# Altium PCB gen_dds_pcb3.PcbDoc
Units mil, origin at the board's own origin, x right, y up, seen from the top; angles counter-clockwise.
Board outline 6000 x 4000 mil, 2 copper layers (Top Layer, Bottom Layer); 13 components, 10 nets, 45 pads, 6 vias.
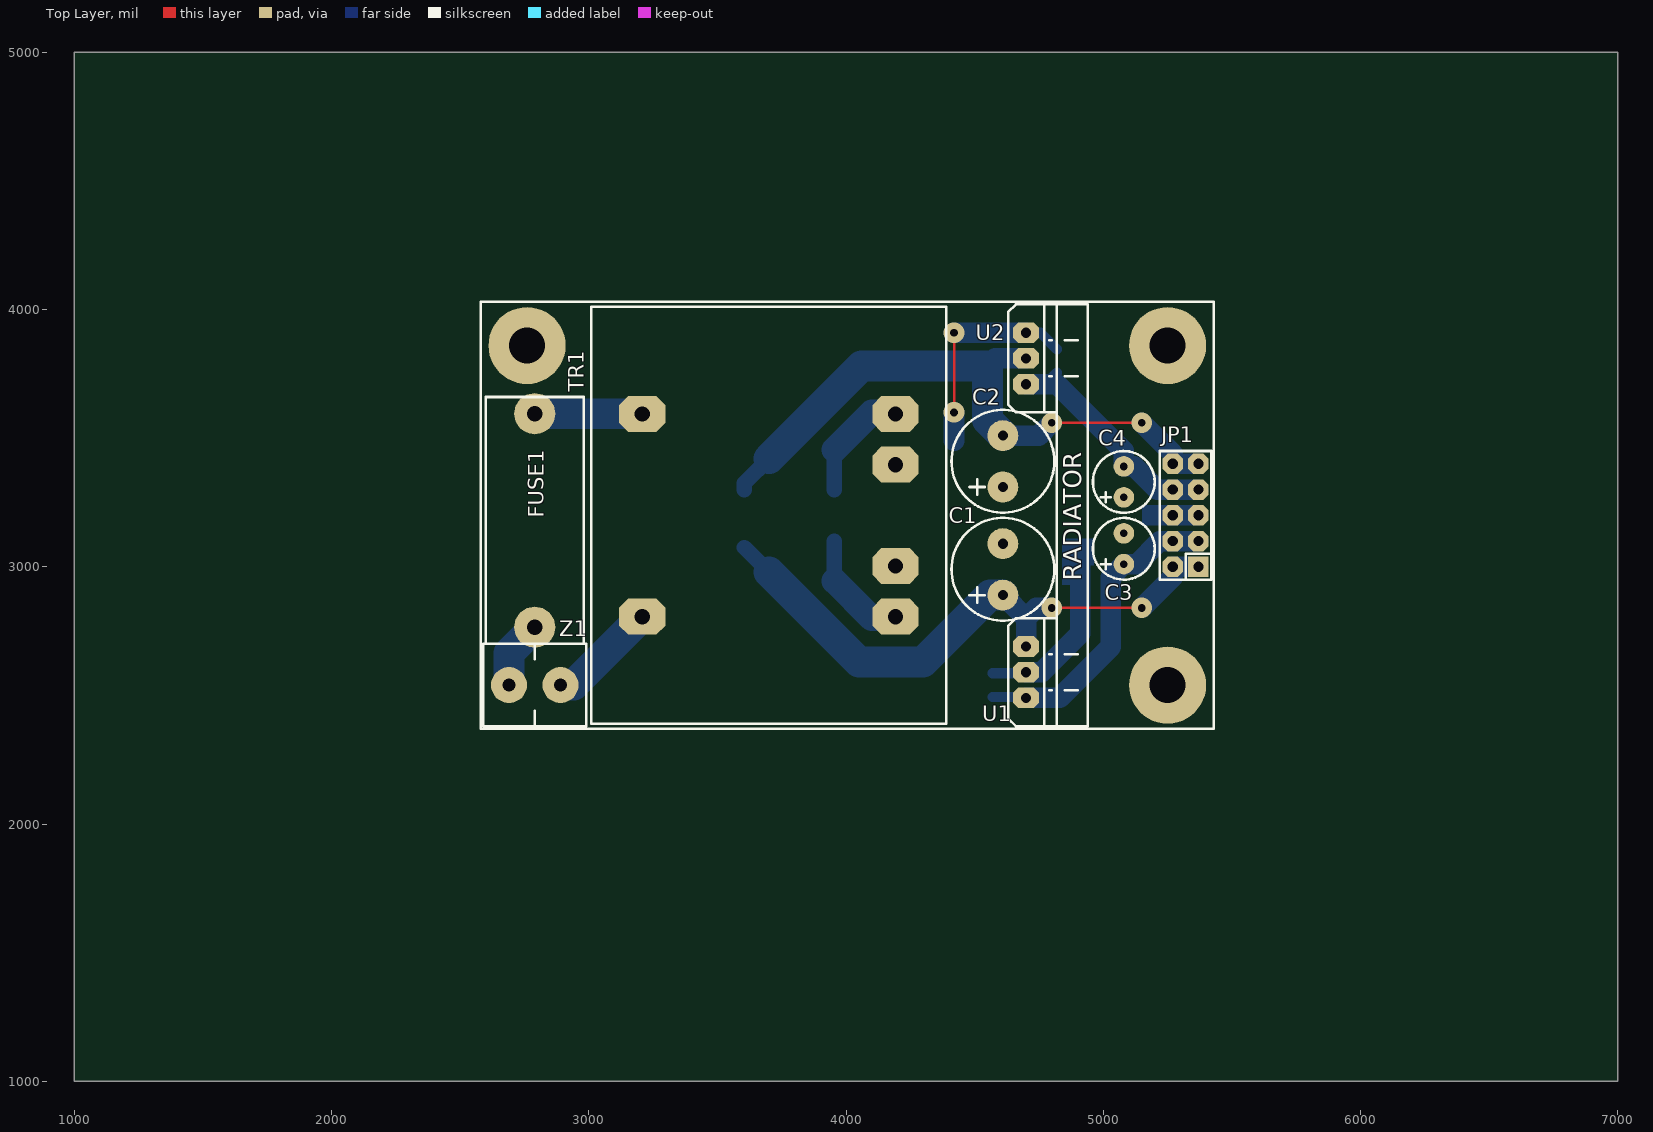
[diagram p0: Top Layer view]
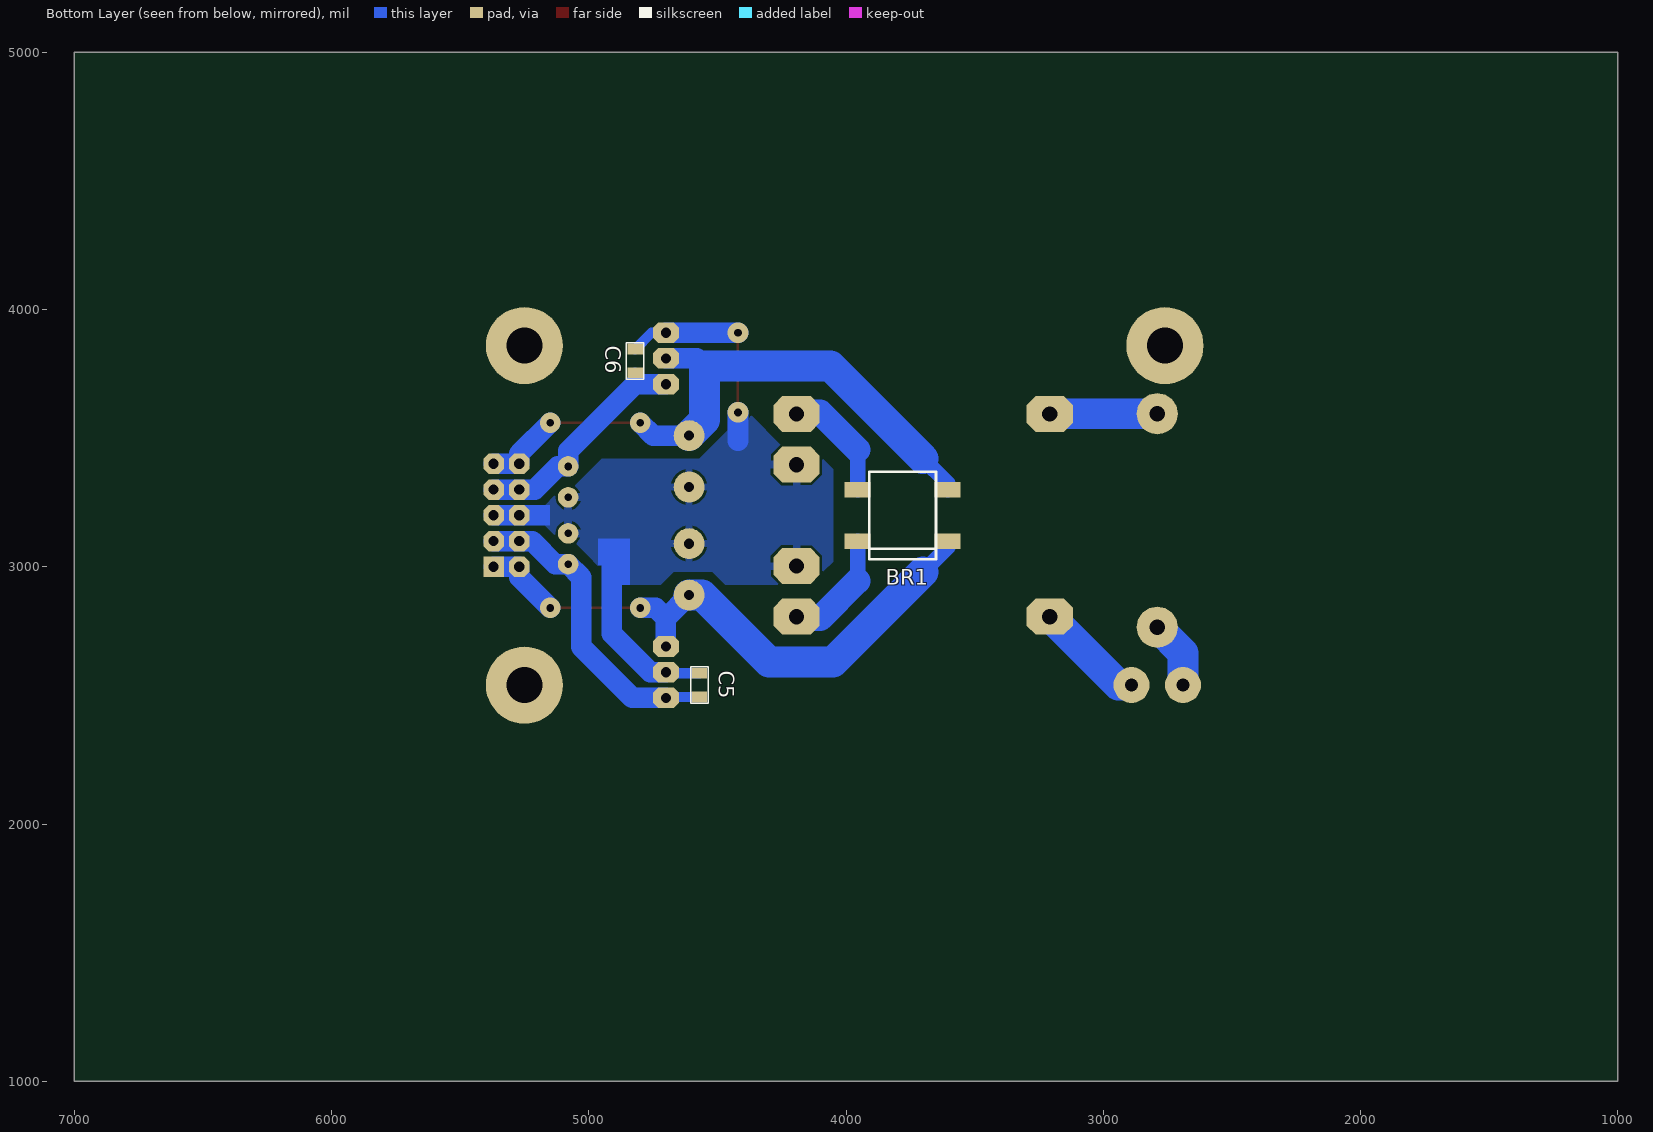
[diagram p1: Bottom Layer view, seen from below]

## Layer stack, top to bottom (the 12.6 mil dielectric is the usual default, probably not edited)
Top Layer: signal copper 1.4
Dielectric: dielectric 12.6, FR-4, Dk 4.8
Bottom Layer: signal copper 1.4

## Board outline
1000,1000 7000,1000 7000,5000 1000,5000

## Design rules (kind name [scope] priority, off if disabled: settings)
Clearance [All] p1: gap=10
PlaneConnect [All] p1: planeconnectstyle=Relief reliefexpansion=20 reliefentries=4 reliefconductorwidth=30 reliefairgap=10
PolygonConnect [All] p1: connectstyle=Relief reliefconductorwidth=30 reliefentries=4 polygonreliefangle="90 Angle"
RoutingVias [All] p1: holewidth=28 width=50 viastyle="Through Hole" minholewidth=28 minwidth=50 maxholewidth=28 maxwidth=50
SilkscreenOverComponentPads [All] p1: minsilkscreentomaskgap=10
SolderMaskExpansion [All] p1: expansion=4
Width [All] p1: maxlimit=200 minlimit=10 preferedwidth=40 toplayer_maxwidth=10 toplayer_prefwidth=10 bottomlayer_minwidth=20 minimp=50.000000 maximp=50.000000 favimp=50.000000
26 further rules are at their usual default settings.

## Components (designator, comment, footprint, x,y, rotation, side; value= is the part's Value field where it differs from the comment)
BR1 "SDB106" SDB1 3780,3200 r0 bottom
C1 "1500u" CE10 4610,2990 r90 top
C2 "1500u" CE10 4610,3410 r90 top
C3 "100u" CE6 5080,3070 r90 top
C4 "100u" CE6 5080,3330 r90 top
C5 "100n" 0805 4570,2540 r90 bottom
C6 "100n" 0805 4820,3800 r270 bottom
FUSE1 "250mA" FUSE 2790,3180 r90 top
JP1 "G2*5" G2*5 5370,3000 r180 top
TR1 "V38AJ-14D06P7" V38AJ-14D06P7 3700,3200 r0 top
U1 "7805" TO220V 4700,2590 r270 top
U2 "7905" TO220V 4700,3810 r270 top
Z1 "ARK2" ARK2 2690,2540 r0 top

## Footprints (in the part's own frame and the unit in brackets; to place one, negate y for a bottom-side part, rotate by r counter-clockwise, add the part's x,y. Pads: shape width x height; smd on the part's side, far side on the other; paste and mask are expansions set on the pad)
0805 [mil]
  rect 42x60 smd: 1(-46,0) 2(46,0)
  silkscreen extent -71,-34 71,34
ARK2 [mil]
  round 140 hole 50: 1(0,0) 2(200,0)
  silkscreen extent -100,-160 300,160
CE6 [mil] "6mm, raster 3mm, pad 2mm"
  round 80 hole 30: 1(-60,0) 2(60,0)
  silkscreen extent -120,-120 120,120
CE10 [mil] "10mm, raster 5mm, pad 3mm"
  round 120 hole 40: 1(-100,0) 2(100,0)
  silkscreen extent -200,-200 200,200
FUSE [mil]
  round 160 hole 60: 1(-415,0) 2(415,0)
  silkscreen extent -480,-190 480,190
G2*5 [mil]
  rect 80x80 hole 40: 1(0,0)
  oct 80x80 hole 40: 2(100,0) 3(0,-100) 4(100,-100) 5(0,-200) 6(100,-200) 7(0,-300) 8(100,-300) 9(0,-400) 10(100,-400)
  silkscreen extent -50,-450 150,50
SDB1 [mil]
  rect 100x60 smd: 1(175,-100) 2(175,100) 3(-175,100) 4(-175,-100)
  silkscreen extent -130,-170 130,170
TO220V [mil]
  oct 80x100 hole 40: 1(-100,0) 2(0,0) 3(100,0)
  silkscreen extent -210,-70 210,120
V38AJ-14D06P7 [mil]
  oct 180x140 hole 60 unplated: 1(-492.5,394) 2(-492.5,-394) 3(492.5,394) 4(492.5,197) 5(492.5,-197) 6(492.5,-394)
  silkscreen extent -690,-810 690,810

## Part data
BR1: library part "MOSTEK GRETZA"
C1 C2 C3 C4: library part CE
C5 C6: library part C
FUSE1: library part FUSE
TR1: library part TRANSFORMATOR2

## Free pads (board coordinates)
  round 300 hole 140: 0(2760,3860) 1(5250,3860) 2(5250,2540)

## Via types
v1: diameter 80, hole 30, Top Layer to Bottom Layer, 6 vias

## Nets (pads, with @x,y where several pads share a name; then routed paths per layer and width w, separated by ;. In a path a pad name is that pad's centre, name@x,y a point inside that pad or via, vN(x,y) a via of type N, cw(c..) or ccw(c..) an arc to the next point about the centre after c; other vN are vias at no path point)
+5V: C3.1 C5.1 JP1.3 JP1.4 U1.3 | length 1206.8
  Bottom Layer w40: C5.1 U1.3@4696,2494
  Bottom Layer w80: U1.3 4830,2490 5030,2690 5030,2960 C3.1 5130,3010 5220,3100 JP1.4 JP1.3
+ZAS: BR1.3 C1.1 JP1.1 JP1.2 U1.1 | length 2310.6
  Top Layer w10: v1(4800,2840) v1(5150,2840)
  Bottom Layer w60: BR1.3@3605,3075 3700,2980
  Bottom Layer w80: C1.1 4700,2800 ; U1.1 4700,2800 ; v1(4800,2840) 4740,2840 4700,2800 ; v1(5150,2840) 5270,2960 JP1.2 JP1.1
  Bottom Layer w120: 3700,2980 4050,2630 4300,2630 4560,2890 C1.1
-5V: C4.2 C6.2 JP1.7 JP1.8 U2.3 | length 937.2
  Bottom Layer w40: 4776,3710 C6.2
  Bottom Layer w80: U2.3 4776,3710 4820,3710 5080,3450 C4.2 5120,3390 5210,3300 JP1.8 JP1.7
-ZAS: BR1.4 C2.2 JP1.9 JP1.10 U2.2 | length 2486.2
  Top Layer w10: v1(4800,3560) v1(5150,3560)
  Bottom Layer w60: BR1.4 3605,3325 3700,3420
  Bottom Layer w80: 4550,3780 4580,3810 U2.2 ; C2.2 4750,3510 v1(4800,3560) ; v1(5150,3560) 5270,3440 JP1.10 JP1.9
  Bottom Layer w120: 3700,3420 4060,3780 4550,3780 4550,3570 C2.2
GND: C1.2 C2.1 C3.2 C4.1 C5.2 C6.1 JP1.5 JP1.6 TR1.4 TR1.5 U1.2 U2.1 | length 1604.6
  Top Layer w10: v1(4420,3600) v1(4420,3910)
  Bottom Layer w40: C5.2 U1.2@4696,2586 ; U2.1 4756,3910 C6.1
  Bottom Layer w80: 4420,3490 v1(4420,3600) ; v1(4420,3910) U2.1 ; U1.2 4760,2590 4910,2740 4910,3000 ; JP1.6 JP1.5
NetBR1_1: BR1.1 TR1.3 | length 446.6
  Bottom Layer w60: BR1.1 3955,3455
  Bottom Layer w100: 3955,3455 4100,3600 TR1.3@4186.5,3600
NetBR1_2: BR1.2 TR1.6 | length 455
  Bottom Layer w60: 3955,2945 BR1.2 ; TR1.6@4186.5,2800 TR1.6
  Bottom Layer w100: 3955,2945 4100,2800 TR1.6@4186.5,2800
NetFUSE1_1: FUSE1.1 Z1.1 | length 266.4
  Bottom Layer w120: Z1.1 2690,2665 FUSE1.1
NetFUSE1_2: FUSE1.2 TR1.1 | length 417.9
  Bottom Layer w120: FUSE1.2 3206.5,3595 TR1.1
NetTR1_2: TR1.2 Z1.2 | length 427.7
  Bottom Layer w120: Z1.2 2941.5,2540 TR1.2

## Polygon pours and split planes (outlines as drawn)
GND on Bottom Layer "Top Layer-No Net" (solid, pour order 10): 4200,3470 4250,3470 4380,3600 4460,3600 4460,3540 4460,3530 4560,3430 4570,3420 4670,3420 4950,3420 5060,3310 5100,3310 5170,3240 5170,3170 5170,3160 5100,3090 5060,3090 5050,3090 5000,3040 4890,2930 4720,2930 4670,2980 4590,2980 4520,2980 4470,2930 4200,2930 4140,2930 4050,3020 4050,3370 4050,3380 4140,3470 4200,3470

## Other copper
Bottom Layer:
  rectangle net GND: 5150,3160 5270,3240
  rectangle net GND: 4910,3004.38 4964.38,3110
  rectangle net GND: 4840,2930 4950,3110

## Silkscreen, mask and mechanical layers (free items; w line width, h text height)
Top Overlay:
  lines w10: 2590,2380 2990,2380 ; 4820,2380 4940,2380 4940,4000 4940,4020 4820,4020 ; 4820,2800 4820,3600 ; 4850,2520 4900,2520 ; 4850,2660 4900,2660 ; 4850,3740 4900,3740 ; 4850,3880 4900,3880 ; 2580,2370 5430,2370 5430,4030 2580,4030 2580,2370
  text "RADIATOR" at 4915,2945 h70 r90
Mechanical 1:
  lines w10: 2565,2355 5445,2355 5445,4045 2565,4045 2565,2355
